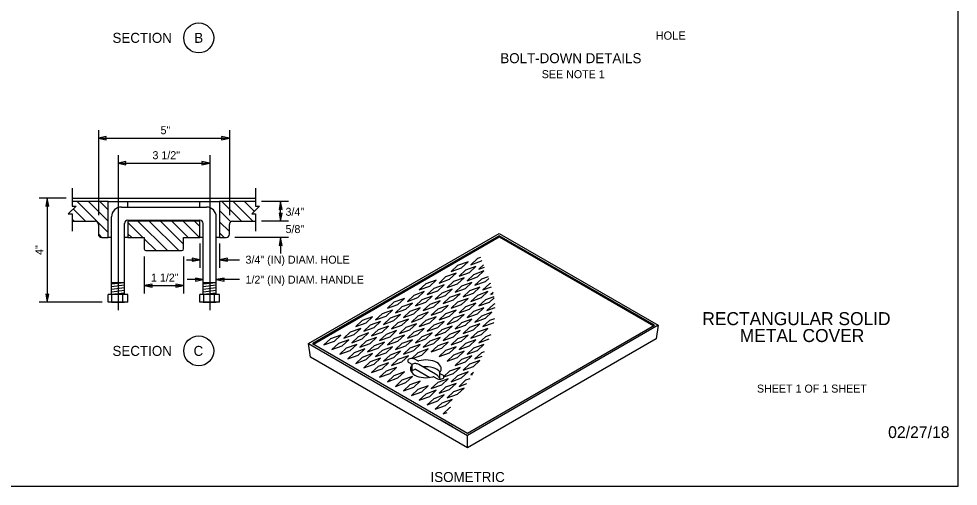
# Model space of a CAD drawing. Extents: x 99862 to 103151, y 100000 to 102076.
# Drawn here: x 101271 to 103151, y 100000 to 100935 of the extents above; entities that cross this region are included whole.
import ezdxf

# ---------------------------------------------------------------- set-up
doc = ezdxf.new("R2010")
doc.units = 0
for name, color, linetype in [('Level 1', 7, 'Continuous'), ('Level 15', 7, 'Continuous'), ('Level 17', 7, 'Continuous'), ('Level 18', 7, 'Continuous'), ('Level 20', 7, 'Continuous'), ('Level 3', 7, 'Continuous'), ('Level 6', 7, 'Continuous'), ('Level 62', 7, 'Continuous'), ('Level 9', 7, 'Continuous')]:
    doc.layers.add(name, color=color, linetype=linetype)

msp = doc.modelspace()

# ---------------------------------------------------------------- linework, layer by layer
at = {"layer": 'Level 1'}
for p, q in [((101377.8, 100575.7), (101744.7, 100575.7)), ((101449.9, 100569.1), (101672.7, 100569.1)), ((101489.2, 100558), (101489.2, 100569.1)), ((101633.3, 100558), (101633.3, 100569.1)), ((101476.1, 100558), (101646.5, 100558)), ((101456.4, 100382.7), (101456.4, 100538.3)), ((101489.2, 100531.8), (101633.3, 100531.8)), ((101666.1, 100382.7), (101666.1, 100538.3)), ((101482.6, 100382.7), (101482.6, 100525.2)), ((101639.9, 100382.7), (101639.9, 100525.2)), ((101456.4, 100497), (101449.9, 100497)), ((101489.2, 100497), (101482.6, 100497)), ((101639.9, 100497), (101633.3, 100497)), ((101672.7, 100497), (101666.1, 100497)), ((101482.6, 100406.6), (101456.4, 100406.6)), ((101482.6, 100406.6), (101456.4, 100403.7)), ((101482.6, 100401.4), (101456.4, 100398.5)), ((101666.1, 100406.6), (101639.9, 100406.6)), ((101666.1, 100406.6), (101639.9, 100403.7)), ((101666.1, 100401.4), (101639.9, 100398.5)), ((101449.9, 100368), (101449.9, 100382.7)), ((101489.2, 100382.7), (101449.9, 100382.7)), ((101482.6, 100396.1), (101456.4, 100393.2)), ((101482.6, 100390.9), (101456.4, 100388)), ((101482.6, 100385.6), (101456.4, 100382.7)), ((101457.4, 100368), (101457.4, 100382.7)), ((101479, 100368), (101479, 100382.7)), ((101489.2, 100368), (101489.2, 100382.7)), ((101633.4, 100368), (101633.4, 100382.7)), ((101672.7, 100382.7), (101633.4, 100382.7)), ((101666.1, 100396.1), (101639.9, 100393.2)), ((101666.1, 100390.9), (101639.9, 100388)), ((101666.1, 100385.6), (101639.9, 100382.7)), ((101640.9, 100368), (101640.9, 100382.7)), ((101662.5, 100368), (101662.5, 100382.7)), ((101672.7, 100368), (101672.7, 100382.7)), ((101489.2, 100368), (101449.9, 100368)), ((101456.4, 100368), (101482.6, 100368)), ((101672.7, 100368), (101633.4, 100368)), ((101639.9, 100368), (101666.1, 100368))]:
    msp.add_line(p, q, dxfattribs=at)
for points in [[(99862, 99999.5), (103151, 99999.5), (103151, 102075.5), (99862, 102075.5)], [(101430.2, 100695.7), (101445.9, 100692.6), (101445.2, 100695.7), (101445.9, 100698.8)], [(101692.3, 100695.7), (101676.6, 100698.8), (101677.3, 100695.7), (101676.6, 100692.6)], [(101469.5, 100645.7), (101485.2, 100642.6), (101484.5, 100645.7), (101485.2, 100648.8)], [(101653, 100645.7), (101637.3, 100648.8), (101638, 100645.7), (101637.3, 100642.6)], [(101327.8, 100575.7), (101324.7, 100559.9), (101327.8, 100560.7), (101330.8, 100559.9)], [(101794.8, 100569.1), (101791.7, 100553.4), (101794.8, 100554.1), (101797.8, 100553.4)], [(101794.8, 100529.8), (101797.8, 100545.5), (101794.8, 100544.8), (101791.7, 100545.5)], [(101794.8, 100497), (101791.7, 100481.3), (101794.8, 100482), (101797.8, 100481.3)], [(101633.3, 100452.7), (101617.6, 100455.7), (101618.3, 100452.7), (101617.6, 100449.6)], [(101672.7, 100452.7), (101688.4, 100449.6), (101687.7, 100452.7), (101688.4, 100455.7)], [(101521.9, 100400.8), (101537.7, 100397.7), (101536.9, 100400.8), (101537.7, 100403.9)], [(101600.6, 100400.8), (101584.9, 100403.9), (101585.6, 100400.8), (101584.9, 100397.7)], [(101639.9, 100412.7), (101624.2, 100415.7), (101624.9, 100412.7), (101624.2, 100409.6)], [(101666.1, 100412.7), (101681.8, 100409.6), (101681.1, 100412.7), (101681.8, 100415.7)], [(101327.8, 100368), (101330.8, 100383.7), (101327.8, 100383), (101324.7, 100383.7)]]:
    msp.add_lwpolyline(points, close=True, dxfattribs=at)
for centre, radius, start, end in [((101476.1, 100538.3), 19.7, 90, 180), ((101646.4, 100538.3), 19.7, 0, 90), ((101489.2, 100525.2), 6.55, 90, 180), ((101633.3, 100525.2), 6.55, 0, 90)]:
    msp.add_arc(centre, radius, start, end, dxfattribs=at)
at = {"layer": 'Level 15'}
for p, q in [((101430.2, 100711.7), (101430.2, 100541.8)), ((101692.3, 100711.7), (101692.3, 100541.8)), ((101430.2, 100695.7), (101692.3, 100695.7)), ((101469.5, 100661.7), (101469.5, 100352)), ((101469.5, 100645.7), (101653, 100645.7)), ((101653, 100661.7), (101653, 100352)), ((101365.8, 100575.7), (101311.8, 100575.7)), ((101327.8, 100575.7), (101327.8, 100368)), ((101810.8, 100569.1), (101756.8, 100569.1)), ((101794.8, 100529.8), (101794.8, 100569.1)), ((101810.8, 100529.8), (101756.8, 100529.8)), ((101810.8, 100497), (101703.1, 100497)), ((101794.8, 100497), (101794.8, 100465)), ((101633.3, 100485), (101633.3, 100436.7)), ((101672.7, 100485), (101672.7, 100436.7)), ((101521.9, 100459.2), (101521.9, 100384.8)), ((101600.6, 100459.2), (101600.6, 100384.8)), ((101606.6, 100452.7), (101633.3, 100452.7)), ((101672.7, 100452.7), (101712.6, 100452.7)), ((101521.9, 100400.8), (101600.6, 100400.8)), ((101639.9, 100412.7), (101607.9, 100412.7)), ((101712.6, 100412.7), (101666.1, 100412.7)), ((101437.9, 100368), (101311.8, 100368))]:
    msp.add_line(p, q, dxfattribs=at)
for points in [[(101377.8, 100595.7), (101377.8, 100560), (101385.5, 100560), (101370, 100544.5), (101377.8, 100544.5), (101377.8, 100509.8)], [(101744.8, 100595.7), (101744.8, 100560), (101752.5, 100560), (101737, 100544.5), (101744.8, 100544.5), (101744.8, 100509.8)]]:
    msp.add_lwpolyline(points, dxfattribs=at)
at = {"layer": 'Level 17'}
for p, q in [((101449.9, 100507), (101387.8, 100569.1)), ((101449.9, 100529.7), (101410.4, 100569.1)), ((101449.9, 100552.3), (101433, 100569.1)), ((101716.8, 100529.8), (101677.5, 100569.1)), ((101739.4, 100529.8), (101700.1, 100569.1)), ((101742.2, 100549.7), (101722.8, 100569.1)), ((101404.5, 100529.8), (101379.9, 100554.4)), ((101695.3, 100528.7), (101672.7, 100551.3)), ((101381.8, 100529.8), (101377.8, 100533.9)), ((101519.4, 100497), (101489.2, 100527.2)), ((101568.2, 100470.8), (101509.2, 100529.8)), ((101590.9, 100470.8), (101531.9, 100529.8)), ((101600.6, 100483.7), (101554.5, 100529.8)), ((101609.9, 100497), (101577.1, 100529.8)), ((101632.5, 100497), (101599.8, 100529.8)), ((101633.3, 100518.8), (101622.4, 100529.8)), ((101692.3, 100509), (101672.7, 100528.7)), ((101437.2, 100497), (101430.2, 100504.1)), ((101496.8, 100497), (101489.2, 100504.6)), ((101545.6, 100470.8), (101521.9, 100494.5)), ((101681.7, 100497), (101672.7, 100506.1))]:
    msp.add_line(p, q, dxfattribs=at)
at = {"layer": 'Level 18'}
for points in [[(101436.7, 100497), (101449.9, 100497), (101449.9, 100569.1), (101377.8, 100569.1)], [(101744.8, 100569.1), (101672.7, 100569.1), (101672.7, 100497), (101685.8, 100497)], [(101377.8, 100529.8), (101423.6, 100529.8)], [(101430.2, 100523.2), (101430.2, 100503.6)], [(101600.6, 100474.1), (101600.6, 100497), (101633.3, 100497), (101633.3, 100529.8), (101489.2, 100529.8), (101489.2, 100497), (101521.9, 100497)], [(101692.3, 100503.6), (101692.3, 100523.2)], [(101698.9, 100529.8), (101744.8, 100529.8)], [(101521.9, 100497), (101521.9, 100474.1)], [(101525.2, 100470.8), (101597.3, 100470.8)]]:
    msp.add_lwpolyline(points, dxfattribs=at)
for centre, radius, start, end in [((101423.6, 100523.2), 6.55, 0, 90), ((101698.9, 100523.2), 6.55, 90, 180), ((101436.7, 100503.6), 6.55, 180, 270), ((101685.8, 100503.6), 6.55, 270, 360), ((101525.2, 100474.1), 3.28, 180, 270), ((101597.3, 100474.1), 3.28, 270, 360)]:
    msp.add_arc(centre, radius, start, end, dxfattribs=at)
at = {"layer": 'Level 20'}
msp.add_circle((101631, 100270.2), 30, dxfattribs=at)
at = {"layer": 'Level 3'}
for p, q in [((102232.6, 100500.7), (101858.7, 100284.9)), ((101860.7, 100283.7), (102232.6, 100498.4)), ((102542.9, 100321.6), (102232.6, 100500.7)), ((102232.6, 100500.7), (102232.6, 100498.4)), ((102232.6, 100498.4), (102540.9, 100320.4)), ((102169, 100105.7), (102542.9, 100321.6)), ((101858.7, 100284.9), (102169, 100105.7)), ((102121.7, 100218.2), (102121.7, 100218.3)), ((102114.4, 100132.7), (102138.6, 100118.7))]:
    msp.add_line(p, q, dxfattribs=at)
for points in [[(102195.1, 100457), (102188.9, 100454.8), (102175.9, 100442.7), (102196.8, 100450.2), (102197.6, 100450.9)], [(102201.1, 100442.2), (102191.8, 100433.6), (102203, 100437.5)], [(102210.4, 100418.3), (102196.8, 100413.5), (102183.9, 100401.4), (102204.8, 100408.9), (102211.5, 100415.2)], [(102214.9, 100405.1), (102212.7, 100404.3), (102199.8, 100392.2), (102217, 100398.4)], [(102220, 100387), (102215.7, 100383), (102220.5, 100384.8)], [(102221.9, 100378.2), (102204.8, 100372.1), (102191.9, 100360.1), (102212.7, 100367.5), (102222.2, 100376.4)], [(102223.9, 100364.1), (102220.7, 100362.9), (102207.8, 100350.9), (102224.3, 100356.8)], [(102222.7, 100334.3), (102212.7, 100330.8), (102199.8, 100318.7), (102220.7, 100326.2), (102221.4, 100326.9)], [(102215.3, 100302.4), (102204.8, 100298.6), (102191.9, 100286.6), (102212.6, 100294)], [(102058.9, 100255.3), (102077.5, 100261.9), (102090.4, 100274), (102069.5, 100266.5), (102057.6, 100255.3)], [(102202.5, 100268.5), (102196.8, 100266.5), (102183.9, 100254.4), (102198.3, 100259.6)], [(102121.8, 100218.3), (102141.1, 100225.2), (102154.1, 100237.2), (102133.2, 100229.7), (102121.8, 100219.1)], [(102173.3, 100214.3), (102165, 100211.4), (102152.1, 100199.3), (102167.3, 100204.8)], [(102180.8, 100226.8), (102175.9, 100222.3), (102178.7, 100223.3)], [(102135, 100156.9), (102133.2, 100156.3), (102120.3, 100144.2), (102128, 100147)]]:
    msp.add_lwpolyline(points, dxfattribs=at)
for points in [[(102157, 100436.4), (102170, 100448.5), (102149.1, 100441), (102136.2, 100429)], [(102173, 100427.2), (102185.9, 100439.3), (102165, 100431.8), (102152.1, 100419.8)], [(102133.2, 100413.5), (102146.1, 100425.5), (102125.2, 100418.1), (102112.3, 100406)], [(102188.9, 100418.1), (102201.8, 100430.1), (102180.9, 100422.6), (102168, 100410.6)], [(102093.4, 100399.7), (102106.3, 100411.7), (102085.5, 100404.3), (102072.5, 100392.2)], [(102109.3, 100390.5), (102122.2, 100402.6), (102101.4, 100395.1), (102088.4, 100383)], [(102149.1, 100404.3), (102162, 100416.3), (102141.1, 100408.9), (102128.2, 100396.8)], [(102165, 100395.1), (102177.9, 100407.1), (102157, 100399.7), (102144.1, 100387.6)], [(102069.5, 100376.7), (102082.5, 100388.8), (102061.6, 100381.3), (102048.7, 100369.3)], [(102125.2, 100381.3), (102138.2, 100393.4), (102117.3, 100385.9), (102104.3, 100373.8)], [(102141.1, 100372.1), (102154.1, 100384.2), (102133.2, 100376.7), (102120.3, 100364.7)], [(102180.9, 100385.9), (102193.8, 100398), (102173, 100390.5), (102160, 100378.4)], [(102196.8, 100376.7), (102209.7, 100388.8), (102188.9, 100381.3), (102175.9, 100369.3)], [(102029.8, 100362.9), (102042.7, 100375), (102021.8, 100367.5), (102008.9, 100355.5)], [(102045.7, 100353.8), (102058.6, 100365.8), (102037.7, 100358.3), (102024.8, 100346.3)], [(102085.5, 100367.5), (102098.4, 100379.6), (102077.5, 100372.1), (102064.6, 100360.1)], [(102101.4, 100358.3), (102114.3, 100370.4), (102093.4, 100362.9), (102080.5, 100350.9)], [(102157, 100362.9), (102170, 100375), (102149.1, 100367.5), (102136.2, 100355.5)], [(102173, 100353.8), (102185.9, 100365.8), (102165, 100358.3), (102152.1, 100346.3)], [(102005.9, 100340), (102018.8, 100352), (101997.9, 100344.6), (101985, 100332.5)], [(102021.8, 100330.8), (102034.7, 100342.8), (102013.9, 100335.4), (102000.9, 100323.3)], [(102061.6, 100344.6), (102074.5, 100356.6), (102053.6, 100349.2), (102040.7, 100337.1)], [(102077.5, 100335.4), (102090.4, 100347.4), (102069.5, 100340), (102056.6, 100327.9)], [(102117.3, 100349.2), (102130.2, 100361.2), (102109.3, 100353.8), (102096.4, 100341.7)], [(102133.2, 100340), (102146.1, 100352), (102125.2, 100344.6), (102112.3, 100332.5)], [(102149.1, 100330.8), (102162, 100342.8), (102141.1, 100335.4), (102128.2, 100323.3)], [(102188.9, 100344.6), (102201.8, 100356.6), (102180.9, 100349.2), (102168, 100337.1)], [(102204.8, 100335.4), (102217.7, 100347.4), (102196.8, 100340), (102183.9, 100327.9)], [(101966.1, 100326.2), (101979.1, 100338.3), (101958.2, 100330.8), (101945.2, 100318.7)], [(101982, 100317), (101995, 100329.1), (101974.1, 100321.6), (101961.2, 100309.5)], [(102037.7, 100321.6), (102050.6, 100333.7), (102029.8, 100326.2), (102016.8, 100314.1)], [(102053.6, 100312.4), (102066.6, 100324.5), (102045.7, 100317), (102032.7, 100305)], [(102093.4, 100326.2), (102106.3, 100338.3), (102085.5, 100330.8), (102072.5, 100318.7)], [(102109.3, 100317), (102122.2, 100329.1), (102101.4, 100321.6), (102088.4, 100309.5)], [(102165, 100321.6), (102177.9, 100333.7), (102157.1, 100326.2), (102144.1, 100314.1)], [(102180.9, 100312.4), (102193.8, 100324.5), (102173, 100317), (102160, 100305)], [(101942.3, 100303.2), (101955.2, 100315.3), (101934.3, 100307.8), (101921.4, 100295.8)], [(101958.2, 100294.1), (101971.1, 100306.1), (101950.2, 100298.6), (101937.3, 100286.6)], [(101997.9, 100307.8), (102010.9, 100319.9), (101990, 100312.4), (101977.1, 100300.4)], [(102013.9, 100298.6), (102026.8, 100310.7), (102005.9, 100303.2), (101993, 100291.2)], [(102069.5, 100303.2), (102082.5, 100315.3), (102061.6, 100307.8), (102048.7, 100295.8)], [(102085.5, 100294), (102098.4, 100306.1), (102077.5, 100298.6), (102064.6, 100286.6)], [(102125.2, 100307.8), (102138.2, 100319.9), (102117.3, 100312.4), (102104.3, 100300.4)], [(102141.1, 100298.6), (102154.1, 100310.7), (102133.2, 100303.2), (102120.3, 100291.2)], [(102196.8, 100303.2), (102209.8, 100315.3), (102188.9, 100307.8), (102175.9, 100295.8)], [(101902.5, 100289.5), (101915.4, 100301.5), (101894.5, 100294), (101881.6, 100282)], [(101918.4, 100280.3), (101931.3, 100292.3), (101910.4, 100284.9), (101897.5, 100272.8)], [(101974.1, 100284.9), (101987, 100296.9), (101966.1, 100289.5), (101953.2, 100277.4)], [(101990, 100275.7), (102002.9, 100287.7), (101982, 100280.3), (101969.1, 100268.2)], [(102029.8, 100289.5), (102042.7, 100301.5), (102021.8, 100294), (102008.9, 100282)], [(102045.7, 100280.3), (102058.6, 100292.3), (102037.7, 100284.9), (102024.8, 100272.8)], [(102101.4, 100284.9), (102114.3, 100296.9), (102093.4, 100289.5), (102080.5, 100277.4)], [(102117.3, 100275.7), (102130.2, 100287.7), (102109.3, 100280.3), (102096.4, 100268.2)], [(102157.1, 100289.4), (102170, 100301.5), (102149.1, 100294), (102136.2, 100282)], [(102173, 100280.3), (102185.9, 100292.3), (102165, 100284.9), (102152.1, 100272.8)], [(101934.3, 100271.1), (101947.2, 100283.1), (101926.4, 100275.7), (101913.4, 100263.6)], [(101950.2, 100261.9), (101963.1, 100274), (101942.3, 100266.5), (101929.3, 100254.4)], [(102005.9, 100266.5), (102018.8, 100278.5), (101997.9, 100271.1), (101985, 100259)], [(102021.8, 100257.3), (102034.7, 100269.4), (102013.9, 100261.9), (102000.9, 100249.8)], [(102061.6, 100271.1), (102074.5, 100283.1), (102053.6, 100275.7), (102040.7, 100263.6)], [(102133.2, 100266.5), (102146.1, 100278.5), (102125.2, 100271.1), (102112.3, 100259)], [(102149.1, 100257.3), (102162, 100269.4), (102141.1, 100261.9), (102128.2, 100249.8)], [(102188.9, 100271.1), (102201.8, 100283.1), (102180.9, 100275.7), (102168, 100263.6)], [(101966.1, 100252.7), (101979.1, 100264.8), (101958.2, 100257.3), (101945.2, 100245.2)], [(101982, 100243.5), (101995, 100255.6), (101974.1, 100248.1), (101961.2, 100236.1)], [(102037.7, 100248.1), (102050.7, 100260.2), (102029.8, 100252.7), (102016.8, 100240.7)], [(102165, 100248.1), (102177.9, 100260.2), (102157.1, 100252.7), (102144.1, 100240.7)], [(102180.9, 100238.9), (102193.8, 100251), (102173, 100243.5), (102160, 100231.5)], [(101998, 100234.3), (102010.9, 100246.4), (101990, 100238.9), (101977.1, 100226.9)], [(102013.9, 100225.2), (102026.8, 100237.2), (102005.9, 100229.7), (101993, 100217.7)], [(102029.8, 100216), (102042.7, 100228), (102021.8, 100220.6), (102008.9, 100208.5)], [(102045.7, 100206.8), (102058.6, 100218.8), (102037.7, 100211.4), (102024.8, 100199.3)], [(102117.3, 100202.2), (102130.2, 100214.2), (102109.3, 100206.8), (102096.4, 100194.7)], [(102157.1, 100216), (102170, 100228), (102149.1, 100220.6), (102136.2, 100208.5)], [(102061.6, 100197.6), (102074.5, 100209.7), (102053.6, 100202.2), (102040.7, 100190.1)], [(102077.5, 100188.4), (102090.4, 100200.5), (102069.5, 100193), (102056.6, 100180.9)], [(102133.2, 100193), (102146.1, 100205.1), (102125.2, 100197.6), (102112.3, 100185.5)], [(102149.1, 100183.8), (102162, 100195.9), (102141.1, 100188.4), (102128.2, 100176.4)], [(102093.4, 100179.2), (102106.3, 100191.3), (102085.5, 100183.8), (102072.5, 100171.8)], [(102109.3, 100170), (102122.3, 100182.1), (102101.4, 100174.6), (102088.4, 100162.6)], [(102125.2, 100160.8), (102138.2, 100172.9), (102117.3, 100165.4), (102104.4, 100153.4)]]:
    msp.add_lwpolyline(points, close=True, dxfattribs=at)
at = {"layer": 'Level 6'}
for p, q in [((102550.8, 100321.6), (102169, 100101.1)), ((101850.8, 100284.9), (102169, 100101.1)), ((102069.6, 100250.4), (102063.6, 100253.9)), ((102051.7, 100247), (102057.7, 100243.5)), ((102058.1, 100229.3), (102058.1, 100242.9)), ((102065.9, 100232.9), (102093.4, 100217.1)), ((102105, 100223.4), (102071.6, 100242.7)), ((102101.3, 100218.3), (102107.3, 100214.8)), ((102112.8, 100225.8), (102112.8, 100216.2)), ((102119.3, 100221.7), (102113.2, 100225.2)), ((102169.2, 100076), (102169, 100101.1))]:
    msp.add_line(p, q, dxfattribs=at)
msp.add_lwpolyline([(102169.2, 100076), (101855, 100257.4), (101850.8, 100284.9), (102232.6, 100505.3), (102550.8, 100321.6), (102546.8, 100294), (102169.2, 100076)], dxfattribs=at)
for centre, major_axis, start_param, end_param in [((102057.6, 100250.4), (-8.44, 0), 3.92655, 7.069025), ((102070.6, 100250.9), (-1.41, 0), 0.785328, 2.046941), ((102085.5, 100234.3), (-30.9, 0), 2.665448, 5.188533), ((102085.5, 100234.3), (-30.9, 0), 5.807041, 8.330126), ((102056.7, 100242.9), (-1.41, 0), 2.665448, 3.926991), ((102057.6, 100236.8), (8.44, 0), 4.771976, 5.577754), ((102057.6, 100236.8), (8.44, 0), 5.489581, 5.577754), ((102085.5, 100220.7), (30.9, 0), 0.39039, 1.773889), ((102085.5, 100220.7), (30.9, 0), 2.665448, 2.751202), ((102056.7, 100229.3), (1.41, 0), 5.807041, 6.283185), ((102100.3, 100217.7), (-1.41, 0), 3.926991, 5.188533), ((102113.3, 100218.3), (-8.44, 0), 0.78526, 3.927129), ((102114.2, 100225.8), (-1.41, 0), 5.807041, 7.068653)]:
    msp.add_ellipse(centre, major_axis=major_axis, ratio=0.57735, start_param=start_param, end_param=end_param, dxfattribs=at)
for points, degree in [([(102071.6, 100242.7), (102069.2, 100244), (102065.2, 100245.3), (102060.5, 100244.6), (102058.6, 100243.7), (102057.9, 100243.3)], 3), ([(102063.7, 100233.7), (102063.7, 100233.6), (102063.6, 100233.5), (102063.5, 100233.3)], 2), ([(102064, 100233.7), (102063.9, 100233.7), (102063.8, 100233.7), (102063.7, 100233.7)], 2), ([(102064, 100233.7), (102064.1, 100233.6), (102064.6, 100233.6), (102065.3, 100233.3), (102065.9, 100232.9)], 3), ([(102114.6, 100213.4), (102114, 100214.4), (102111.3, 100218.5), (102107.9, 100221.7), (102105, 100223.4)], 3)]:
    msp.add_open_spline(points, degree=degree, dxfattribs=at)
at = {"layer": 'Level 9'}
msp.add_circle((101631, 100896.3), 30, dxfattribs=at)

# ---------------------------------------------------------------- texts
at = {"layer": 'Level 1'}
msp.add_text('HOLE', height=16.5, dxfattribs=at).set_placement((102545.4, 100892.7))
at = {"layer": 'Level 15'}
msp.add_text('02/27/18', height=23.62, dxfattribs=at).set_placement((103010.7, 100095.8))
at = {"layer": 'Level 20'}
for s, height, p in [('SECTION', 20, (101458.4, 100886.5)), ('B', 20, (101622.1, 100886.5)), ('BOLT-DOWN DETAILS', 20, (102234.6, 100845.8)), ('5"', 16, (101554.6, 100703.7)), ('3 1/2"', 16, (101538.4, 100653.7)), ('3/4"', 16, (101804.7, 100540.5)), ('5/8"', 16, (101804.7, 100505.9)), ('3/4" (IN) DIAM. HOLE', 16, (101724.6, 100444.7)), ('1 1/2"', 16, (101535.4, 100408.8)), ('1/2" (IN) DIAM. HANDLE', 16, (101724.6, 100404.7)), ('SECTION', 20, (101458.4, 100260.2)), ('C', 20, (101620.7, 100260.2)), ('ISOMETRIC', 20, (102094.9, 100007.9))]:
    msp.add_text(s, height=height, dxfattribs=at).set_placement(p)
msp.add_text('4"', height=16, rotation=90, dxfattribs=at).set_placement((101319.8, 100462.2))
at = {"layer": 'Level 62'}
for s, height, p in [('SEE NOTE 1', 16, (102317.5, 100815.8)), ('RECTANGULAR SOLID', 26, (102638.9, 100321.7)), ('METAL COVER', 26, (102713.8, 100287.9)), ('SHEET 1 OF 1 SHEET', 16, (102748.2, 100186.8))]:
    msp.add_text(s, height=height, dxfattribs=at).set_placement(p)

doc.saveas('drawing.dxf')
